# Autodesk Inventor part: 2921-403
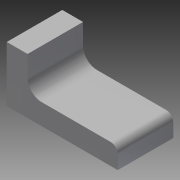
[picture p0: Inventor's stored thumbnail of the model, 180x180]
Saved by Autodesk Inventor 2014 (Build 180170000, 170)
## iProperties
Company: `NHTSA/VRTC
Created: 2012-12
Part Number: 2921-403
Material: Steel, Mild
Document SubType Name: Modeling
Designer: Mike Vanvoorhis
Density: 7.86 g/cm^3
Mass: 129.985 g
Surface Area: 50.7898 cm^2
Volume: 16.5375 cm^3
Project: CHILD SIDE IMPACT SLED
Description: ANTI-REBOUND FIXTURE GUIDE
Stock Number: L2" x 2" x 3/8" x (25.4mm) 1.0"
Appearance: Steel
Author: Dave Walker
Title: Anti-Rebound Fixture Guide
Subject: Child Side Impact Sled
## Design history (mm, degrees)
sketch "Sketch1"
  geometry: L1 (0, 0)-(50.8, 0); L2 (50.8, 0)-(50.8, 9.525); L3 (0, 0)-(0, 25.4); L4 (0, 25.4)-(9.525, 25.4); L5 (9.525, 25.4)-(9.525, 9.525); L6 (9.525, 9.525)-(50.8, 9.525)
  constraints: 12 end point, 3 perpendicular, 2 parallel, 1 horizontal
  dimensions: "d0" = 50.8 distance of L1.start L1.end; "d1" = 9.525 distance of L1.end L2.end; "d2" = 25.4 distance of L1.start L3.end; "d3" = 9.525 distance of L3.end L4.end
extrude "Extrusion1" new body sketch "Sketch1" distance "d4" = 12.7; taper "d6" = 0 deg; dims "d5" = 12.7, "d7" = 0
fillet "Fillet1" dims "d8" = 8.636
fillet "Fillet2" dims "d9" = 3.175
sketch "Sketch2"
  geometry: L1 (18.161, 9.525)-(9.525, 9.525); L2 (9.525, 9.525)-(9.525, 18.161); A1 r 8.636 centre (18.161, 18.161) between (9.525, 18.161) and (18.161, 9.525) reference; A2 r 8.636 centre (18.161, 18.161) between (9.525, 18.161) and (18.161, 9.525)
  constraints: 4 end point, 2 point on circle, 1 centre point, 1 coincident, 1 horizontal, 1 vertical
extrude "Extrusion2" cut sketch "Sketch2" stored distance "d10" = 25.4; taper "d11" = 0 deg
fillet "Fillet3" dims "d12" = 6.35
body "Solid1"
